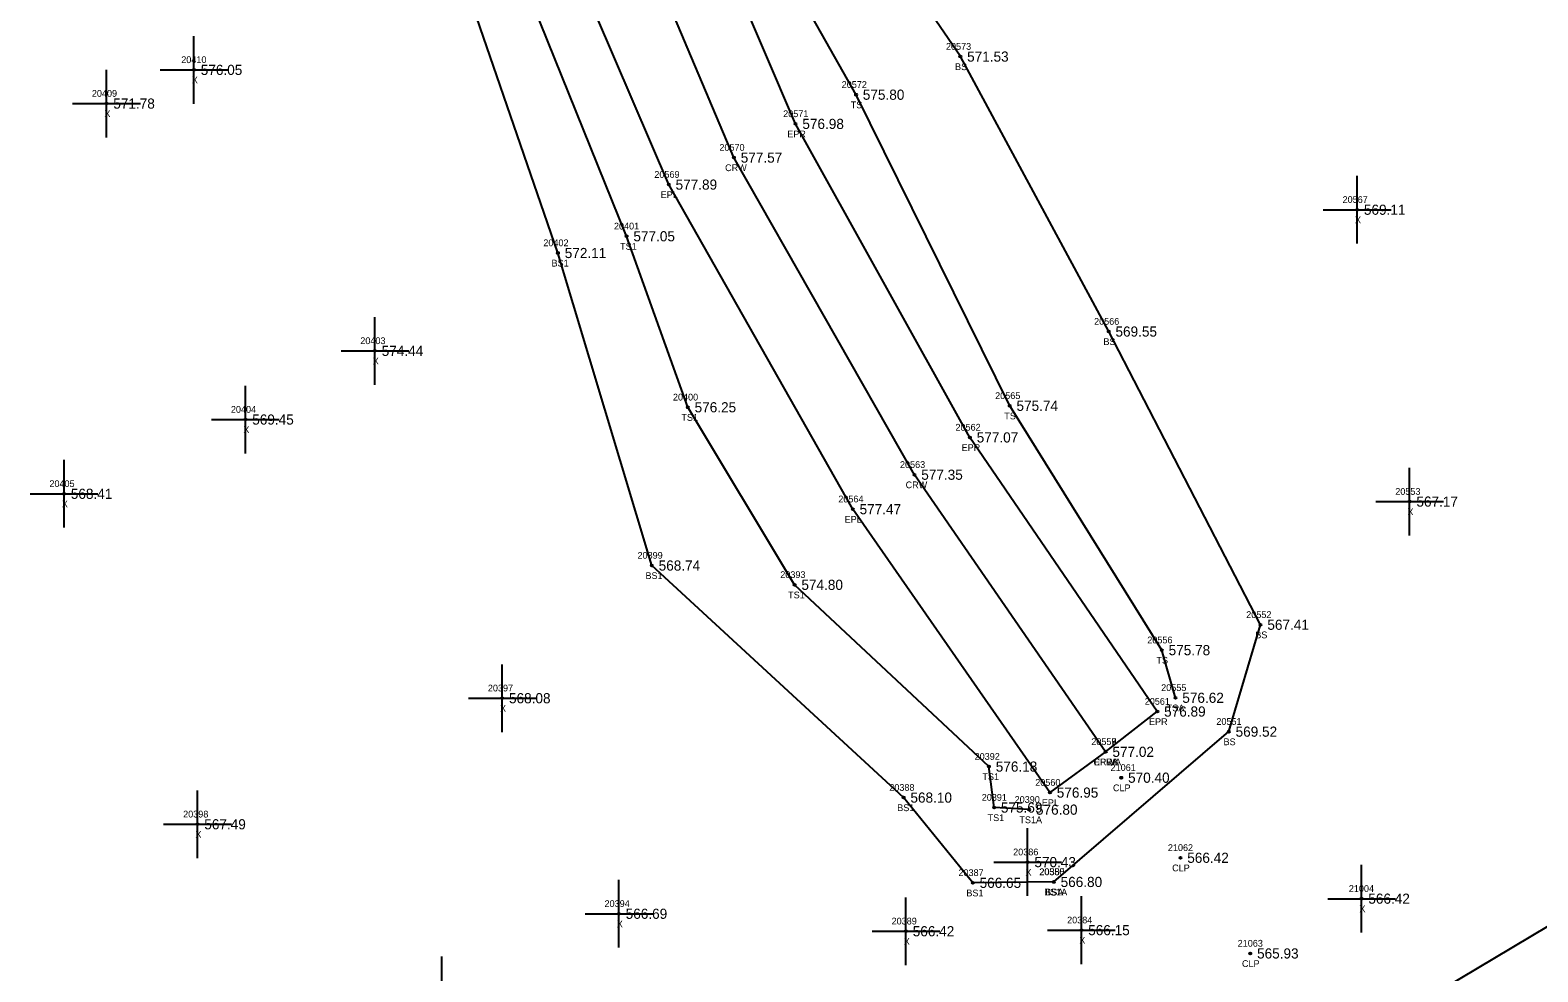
# Model space of a CAD drawing. Extents: x 1695443 to 1696344, y 1087542 to 1090645.
# Drawn here: x 1695655 to 1695877.6, y 1089115.6 to 1089254.7 of the extents above; entities that cross this region are included whole.
import ezdxf

# ---------------------------------------------------------------- set-up
doc = ezdxf.new("R2010")
doc.units = 0
for name, color, linetype in [('RD_DTM_BkLn1', 7, 'Continuous'), ('RD_DTM_BkLn2', 7, 'Continuous'), ('RD_DTM_BkLn_txCode', 7, 'Continuous'), ('RD_EX_H2O', 7, 'Continuous'), ('RD_EX_Misc', 7, 'Continuous'), ('RD_EX_Misc_txCode', 7, 'Continuous'), ('RD_EX_Road', 7, 'Continuous'), ('RD_EX_Road_txCode', 7, 'Continuous'), ('RD_EX_TX_Misc_ELEV', 7, 'Continuous'), ('RD_EX_TX_Road_ELEV', 7, 'Continuous'), ('RD_HC_Survey_ELEV', 7, 'Continuous'), ('RD_HC_Survey_txCode', 7, 'Continuous'), ('RD_SMD_Locator', 7, 'Continuous')]:
    doc.layers.add(name, color=color, linetype=linetype)

msp = doc.modelspace()

# ---------------------------------------------------------------- linework, layer by layer
at = {"layer": 'RD_DTM_BkLn1'}
msp.add_lwpolyline([(1695813.78, 1089148.1), (1695785.55, 1089189.03), (1695758.89, 1089235.87), (1695740.64, 1089279.02), (1695725.17, 1089334.02), (1695718.27, 1089382.65), (1695717.41, 1089435.13), (1695722.03, 1089482.62), (1695732.64, 1089534.75), (1695759.85, 1089631.43), (1695787.11, 1089727.89), (1695798.89, 1089774.41), (1695810.31, 1089824.5), (1695818.49, 1089870.61), (1695825.85, 1089922.33), (1695831.69, 1089976.57), (1695835.49, 1090019.27), (1695844.06, 1090117.91), (1695852.56, 1090215.73), (1695861.78, 1090313.02), (1695870.8, 1090411.68), (1695879.44, 1090510.15), (1695888.04, 1090606.94)], dxfattribs=at)
at = {"layer": 'RD_DTM_BkLn2'}
for points in [[(1695802.49, 1089139.56), (1695797.31, 1089139.87), (1695796.55, 1089145.92), (1695767.85, 1089172.77), (1695752.08, 1089198.99), (1695743.04, 1089224.25), (1695723.93, 1089271.63), (1695706.46, 1089330), (1695701.78, 1089380.95), (1695703.12, 1089435.75), (1695708.88, 1089486.48), (1695720.72, 1089539.1), (1695747.1, 1089636.56), (1695773.41, 1089730.59), (1695786.04, 1089777.66), (1695796.55, 1089826.24), (1695804.53, 1089873.75), (1695809.45, 1089923.14)], [(1695824.1, 1089156.08), (1695822.08, 1089163.12), (1695799.61, 1089199.21), (1695776.92, 1089245.16), (1695754.8, 1089284.38), (1695737.73, 1089336.15), (1695730.34, 1089383.59), (1695730.57, 1089435.13), (1695734.2, 1089480.03), (1695745.77, 1089531.16), (1695772.55, 1089627.13), (1695801.84, 1089724.13), (1695813.32, 1089771.8), (1695823.97, 1089812.55), (1695828.38, 1089814.06), (1695832.18, 1089812.32)], [(1695806.13, 1089128.88), (1695831.97, 1089151.08), (1695836.66, 1089166.87), (1695814.23, 1089210.18), (1695792.32, 1089250.79), (1695765.95, 1089289.34), (1695750.81, 1089305.62), (1695742.03, 1089337.12), (1695733.74, 1089383.59), (1695733.01, 1089422.34)], [(1695806.13, 1089128.88), (1695794.16, 1089128.75), (1695783.95, 1089141.34), (1695746.77, 1089175.62), (1695732.9, 1089221.78), (1695716.41, 1089269.71), (1695696.87, 1089328.65)]]:
    msp.add_lwpolyline(points, dxfattribs=at)
at = {"layer": 'RD_EX_H2O'}
msp.add_lwpolyline([(1695741.44, 1088979.77), (1695766.31, 1089008.66), (1695772.21, 1089014.13), (1695837.09, 1089090.39), (1695860.76, 1089111.44), (1695929.31, 1089152.28), (1696035.3, 1089183.03), (1696164.17, 1089149.21), (1696221.7, 1089111.38), (1696248.95, 1089080.06), (1696273.19, 1089047.83), (1696283.59, 1089011.28), (1696295.68, 1088944.39)], dxfattribs=at)
at = {"layer": 'RD_EX_Misc'}
for p, q in [((1695679.15, 1089243.83), (1695679.15, 1089253.83)), ((1695666.23, 1089238.85), (1695666.23, 1089248.85)), ((1695674.15, 1089248.83), (1695684.15, 1089248.83)), ((1695661.23, 1089243.85), (1695671.23, 1089243.85)), ((1695850.92, 1089223.17), (1695850.92, 1089233.17)), ((1695845.92, 1089228.17), (1695855.92, 1089228.17)), ((1695705.87, 1089202.32), (1695705.87, 1089212.32)), ((1695700.87, 1089207.32), (1695710.87, 1089207.32)), ((1695686.75, 1089192.18), (1695686.75, 1089202.18)), ((1695681.75, 1089197.18), (1695691.75, 1089197.18)), ((1695659.96, 1089181.21), (1695659.96, 1089191.21)), ((1695858.67, 1089180.06), (1695858.67, 1089190.06)), ((1695654.96, 1089186.21), (1695664.96, 1089186.21)), ((1695853.67, 1089185.06), (1695863.67, 1089185.06)), ((1695724.67, 1089151.02), (1695724.67, 1089161.02)), ((1695719.67, 1089156.02), (1695729.67, 1089156.02)), ((1695679.67, 1089132.4), (1695679.67, 1089142.4)), ((1695674.67, 1089137.4), (1695684.67, 1089137.4)), ((1695802.26, 1089126.81), (1695802.26, 1089136.81)), ((1695797.26, 1089131.81), (1695807.26, 1089131.81)), ((1695851.57, 1089121.41), (1695851.57, 1089131.41)), ((1695741.9, 1089119.18), (1695741.9, 1089129.18)), ((1695784.29, 1089116.6), (1695784.29, 1089126.6)), ((1695810.2, 1089116.76), (1695810.2, 1089126.76)), ((1695846.57, 1089126.41), (1695856.57, 1089126.41)), ((1695736.9, 1089124.18), (1695746.9, 1089124.18)), ((1695805.2, 1089121.76), (1695815.2, 1089121.76)), ((1695779.29, 1089121.6), (1695789.29, 1089121.6)), ((1695715.74, 1089107.88), (1695715.74, 1089117.88))]:
    msp.add_line(p, q, dxfattribs=at)
at = {"layer": 'RD_EX_Road'}
for points in [[(1695813.78, 1089148.1), (1695805.56, 1089142.08), (1695776.44, 1089183.94), (1695749.27, 1089231.88), (1695730.49, 1089275.72), (1695714.87, 1089332.12), (1695707.87, 1089381.72), (1695706.58, 1089435.34), (1695711.58, 1089484.26), (1695722.15, 1089537.59), (1695749.04, 1089634.88), (1695776.11, 1089730.43), (1695788.13, 1089777.42), (1695798.89, 1089826.76), (1695807.1, 1089870.03), (1695814.71, 1089923.3), (1695820.51, 1089978.16), (1695824.04, 1090019.79), (1695832.76, 1090119.06), (1695841.25, 1090216.76), (1695850.36, 1090314.41), (1695859.24, 1090411.82), (1695868.09, 1090511.63), (1695876.75, 1090608.38)], [(1695813.78, 1089148.1), (1695821.41, 1089154.05), (1695793.74, 1089194.54), (1695767.99, 1089240.85), (1695750.16, 1089282.55), (1695735.35, 1089335.84), (1695728.69, 1089383.6), (1695727.9, 1089434.83)]]:
    msp.add_lwpolyline(points, dxfattribs=at)
at = {"layer": 'RD_SMD_Locator'}
for centre in [(1695792.32, 1089250.79), (1695679.15, 1089248.83), (1695776.92, 1089245.16), (1695666.23, 1089243.85), (1695767.99, 1089240.85), (1695758.89, 1089235.87), (1695749.27, 1089231.88), (1695850.92, 1089228.17), (1695743.04, 1089224.25), (1695732.9, 1089221.78), (1695814.23, 1089210.18), (1695705.87, 1089207.32), (1695752.08, 1089198.99), (1695799.61, 1089199.21), (1695686.75, 1089197.18), (1695793.74, 1089194.54), (1695785.55, 1089189.03), (1695659.96, 1089186.21), (1695776.44, 1089183.94), (1695858.67, 1089185.06), (1695746.77, 1089175.62), (1695767.85, 1089172.77), (1695836.66, 1089166.87), (1695822.08, 1089163.12), (1695724.67, 1089156.02), (1695824.1, 1089156.08), (1695821.41, 1089154.05), (1695831.97, 1089151.08), (1695813.78, 1089148.1), (1695813.78, 1089148.1), (1695813.78, 1089148.1), (1695796.55, 1089145.92), (1695816.09, 1089144.28), (1695805.56, 1089142.08), (1695783.95, 1089141.34), (1695797.31, 1089139.87), (1695802.49, 1089139.56), (1695679.67, 1089137.4), (1695802.26, 1089131.81), (1695824.83, 1089132.45), (1695794.16, 1089128.75), (1695806.13, 1089128.88), (1695806.13, 1089128.88), (1695851.57, 1089126.41), (1695741.9, 1089124.18), (1695784.29, 1089121.6), (1695810.2, 1089121.76), (1695835.14, 1089118.32)]:
    msp.add_circle(centre, 0.15, dxfattribs=at)

# ---------------------------------------------------------------- texts
at = {"layer": 'RD_DTM_BkLn_txCode'}
for s, p in [('20573', (1695790.2, 1089251.79)), ('BS', (1695791.54, 1089248.79)), ('20572', (1695774.8, 1089246.16)), ('TS', (1695776.13, 1089243.16)), ('20401', (1695741.17, 1089225.25)), ('20402', (1695730.74, 1089222.78)), ('TS1', (1695742.08, 1089222.25)), ('BS1', (1695731.95, 1089219.78)), ('20566', (1695812.07, 1089211.18)), ('BS', (1695813.45, 1089208.18)), ('20400', (1695749.88, 1089199.99)), ('20565', (1695797.46, 1089200.21)), ('TS1', (1695751.12, 1089196.99)), ('TS', (1695798.81, 1089197.21)), ('20399', (1695744.65, 1089176.62)), ('BS1', (1695745.82, 1089173.62)), ('20393', (1695765.73, 1089173.77)), ('TS1', (1695766.89, 1089170.77)), ('20552', (1695834.54, 1089167.87)), ('20556', (1695819.93, 1089164.12)), ('BS', (1695835.88, 1089164.87)), ('TS', (1695821.28, 1089161.12)), ('20555', (1695821.98, 1089157.08)), ('TSA', (1695822.81, 1089154.08)), ('20551', (1695830.13, 1089152.08)), ('BS', (1695831.19, 1089149.08)), ('20392', (1695794.43, 1089146.92)), ('TS1', (1695795.58, 1089143.92)), ('20388', (1695781.83, 1089142.34)), ('20391', (1695795.48, 1089140.87)), ('BS1', (1695783, 1089139.34)), ('20390', (1695800.34, 1089140.56)), ('TS1', (1695796.35, 1089137.87)), ('TS1A', (1695801.04, 1089137.56)), ('20387', (1695792.04, 1089129.75)), ('20550', (1695803.97, 1089129.88)), ('20385', (1695804.01, 1089129.88)), ('BS1', (1695793.21, 1089126.75)), ('BS1A', (1695804.69, 1089126.88)), ('BSA', (1695804.86, 1089126.88))]:
    msp.add_text(s, height=1, dxfattribs=at).set_placement(p)
at = {"layer": 'RD_EX_Misc_txCode'}
for s, p in [('20410', (1695677.27, 1089249.83)), ('X', (1695678.83, 1089246.83)), ('20409', (1695664.07, 1089244.85)), ('X', (1695665.92, 1089241.85)), ('20567', (1695848.77, 1089229.17)), ('X', (1695850.6, 1089226.17)), ('20403', (1695703.71, 1089208.32)), ('X', (1695705.55, 1089205.32)), ('20404', (1695684.6, 1089198.18)), ('X', (1695686.44, 1089195.18)), ('20405', (1695657.8, 1089187.21)), ('20553', (1695856.55, 1089186.06)), ('X', (1695659.64, 1089184.21)), ('X', (1695858.35, 1089183.06)), ('20397', (1695722.55, 1089157.02)), ('X', (1695724.35, 1089154.02)), ('20398', (1695677.55, 1089138.4)), ('X', (1695679.36, 1089135.4)), ('20386', (1695800.12, 1089132.81)), ('X', (1695801.94, 1089129.81)), ('21004', (1695849.69, 1089127.41)), ('20394', (1695739.78, 1089125.18)), ('X', (1695851.25, 1089124.41)), ('X', (1695741.59, 1089122.18)), ('20389', (1695782.17, 1089122.6)), ('20384', (1695808.09, 1089122.76)), ('X', (1695783.97, 1089119.6)), ('X', (1695809.89, 1089119.76))]:
    msp.add_text(s, height=1, dxfattribs=at).set_placement(p)
at = {"layer": 'RD_EX_Road_txCode'}
for s, p in [('20571', (1695766.16, 1089241.85)), ('EPR', (1695766.76, 1089238.85)), ('20569', (1695747.13, 1089232.88)), ('EPL', (1695748.07, 1089229.88)), ('20562', (1695791.6, 1089195.54)), ('EPR', (1695792.51, 1089192.54)), ('20564', (1695774.3, 1089184.94)), ('EPL', (1695775.23, 1089181.94)), ('20561', (1695819.55, 1089155.05)), ('EPR', (1695820.18, 1089152.05)), ('20558', (1695811.66, 1089149.1)), ('20559', (1695811.66, 1089149.1)), ('EPRA', (1695812.06, 1089146.1)), ('EPLA', (1695812.08, 1089146.1)), ('20560', (1695803.38, 1089143.08)), ('EPL', (1695804.36, 1089140.08))]:
    msp.add_text(s, height=1, dxfattribs=at).set_placement(p)
at = {"layer": 'RD_EX_TX_Misc_ELEV'}
for s, p in [('571.53', (1695793.32, 1089250.04)), ('576.05', (1695680.15, 1089248.08)), ('571.78', (1695667.23, 1089243.1)), ('575.80', (1695777.92, 1089244.41)), ('569.11', (1695851.92, 1089227.42)), ('577.05', (1695744.04, 1089223.5)), ('572.11', (1695733.9, 1089221.03)), ('569.55', (1695815.23, 1089209.43)), ('574.44', (1695706.87, 1089206.57)), ('576.25', (1695753.08, 1089198.24)), ('575.74', (1695800.61, 1089198.46)), ('569.45', (1695687.75, 1089196.43)), ('568.41', (1695660.96, 1089185.46)), ('567.17', (1695859.67, 1089184.31)), ('568.74', (1695747.77, 1089174.87)), ('574.80', (1695768.85, 1089172.02)), ('567.41', (1695837.66, 1089166.12)), ('575.78', (1695823.08, 1089162.37)), ('568.08', (1695725.67, 1089155.27)), ('576.62', (1695825.1, 1089155.33)), ('569.52', (1695832.97, 1089150.33)), ('576.18', (1695797.55, 1089145.17)), ('568.10', (1695784.95, 1089140.59)), ('575.69', (1695798.31, 1089139.12)), ('576.80', (1695803.49, 1089138.81)), ('567.49', (1695680.67, 1089136.65)), ('570.43', (1695803.26, 1089131.06)), ('566.65', (1695795.16, 1089128)), ('566.80', (1695807.13, 1089128.13)), ('566.80', (1695807.13, 1089128.13)), ('566.42', (1695852.57, 1089125.66)), ('566.69', (1695742.9, 1089123.43)), ('566.42', (1695785.29, 1089120.85)), ('566.15', (1695811.2, 1089121.01))]:
    msp.add_text(s, height=1.5, dxfattribs=at).set_placement(p)
at = {"layer": 'RD_EX_TX_Road_ELEV'}
for s, p in [('576.98', (1695768.99, 1089240.1)), ('577.89', (1695750.27, 1089231.13)), ('577.07', (1695794.74, 1089193.79)), ('577.47', (1695777.44, 1089183.19)), ('576.89', (1695822.41, 1089153.3)), ('577.02', (1695814.78, 1089147.35)), ('577.02', (1695814.78, 1089147.35)), ('576.95', (1695806.56, 1089141.33))]:
    msp.add_text(s, height=1.5, dxfattribs=at).set_placement(p)
at = {"layer": 'RD_HC_Survey_ELEV'}
for s, p in [('577.57', (1695759.89, 1089235.12)), ('577.35', (1695786.55, 1089188.28)), ('577.02', (1695814.78, 1089147.35)), ('570.40', (1695817.09, 1089143.53)), ('566.42', (1695825.83, 1089131.7)), ('565.93', (1695836.14, 1089117.57))]:
    msp.add_text(s, height=1.5, dxfattribs=at).set_placement(p)
at = {"layer": 'RD_HC_Survey_txCode'}
for s, p in [('20570', (1695756.74, 1089236.87)), ('CRW', (1695757.58, 1089233.87)), ('20563', (1695783.41, 1089190.03)), ('CRW', (1695784.24, 1089187.03)), ('20557', (1695811.66, 1089149.1)), ('CRWA', (1695811.97, 1089146.1)), ('21061', (1695814.51, 1089145.28)), ('CLP', (1695814.86, 1089142.28)), ('21062', (1695822.97, 1089133.45)), ('CLP', (1695823.6, 1089130.45)), ('21063', (1695833.28, 1089119.32)), ('CLP', (1695833.91, 1089116.32))]:
    msp.add_text(s, height=1, dxfattribs=at).set_placement(p)

doc.saveas('drawing.dxf')
